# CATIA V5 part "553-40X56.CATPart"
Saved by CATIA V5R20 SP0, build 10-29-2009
Part number: 553-40X56
Definition: NONE
Nomenclature: 553-40X66
Source: Unknown
Description: 553-40X66
Bounding box of the stored display mesh (mm): x 0 to 56, y -29.5 to 29.5, z -29.5 to 29.5
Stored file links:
  C:\Users\Utente\Desktop\IO LAVORO\3D X SITO CF\X SITO\PLASTICA\553\553-40X56.CATPart
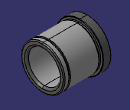
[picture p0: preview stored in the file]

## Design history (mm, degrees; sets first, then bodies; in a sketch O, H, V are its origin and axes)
Body1 "553-40X66" (main body)
  Solid1: solid without history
